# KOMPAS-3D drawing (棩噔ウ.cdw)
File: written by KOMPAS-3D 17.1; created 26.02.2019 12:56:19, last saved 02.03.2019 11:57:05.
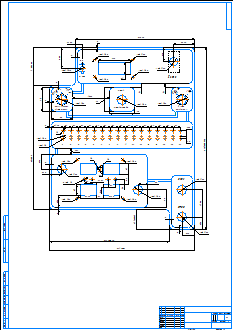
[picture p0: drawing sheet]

Sheet 1: A1, portrait

Title block, sheet 1: scale: 1:1; sheets: 1; sheet format: A1; stored path: C:\Users\kbopt\AppData\Local\Temp\k1kgktsd.cd

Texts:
  Пользователь Windows
  W, Вт.
  Сеть
  Рабочий
  Сервис.
  Выбор режима
  светильника
  Режим
  управления
  Ручной
  Авто
  Готовность ИП
  Готов
  ПУСК
  СТОП
  Отв.
  отв.
Dimensions and other numbers on the sheet: 0; 1; 2; 3; 4; 5; 6; 7; 8; 9; 10; 11; 12; 13; 14; 15; 16; 369,7±0,7; 302,85; 98±0,435; 306,7±0,65; 463,93±0,775; 316±0,7; 49,93±0,31; 23; 10,5; 3,2; 81,5; 29; 53,5; 17,25; 36,5; 52,85; 95,35; 53; 61; 63; 29,85; 20; 2,5; 13,5; 6,5; 14,6; 37,5; 31,5; 25; 45,8; 4 отв.; 40,75; 31,3; 24; 10,38; 69,25; 1:1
